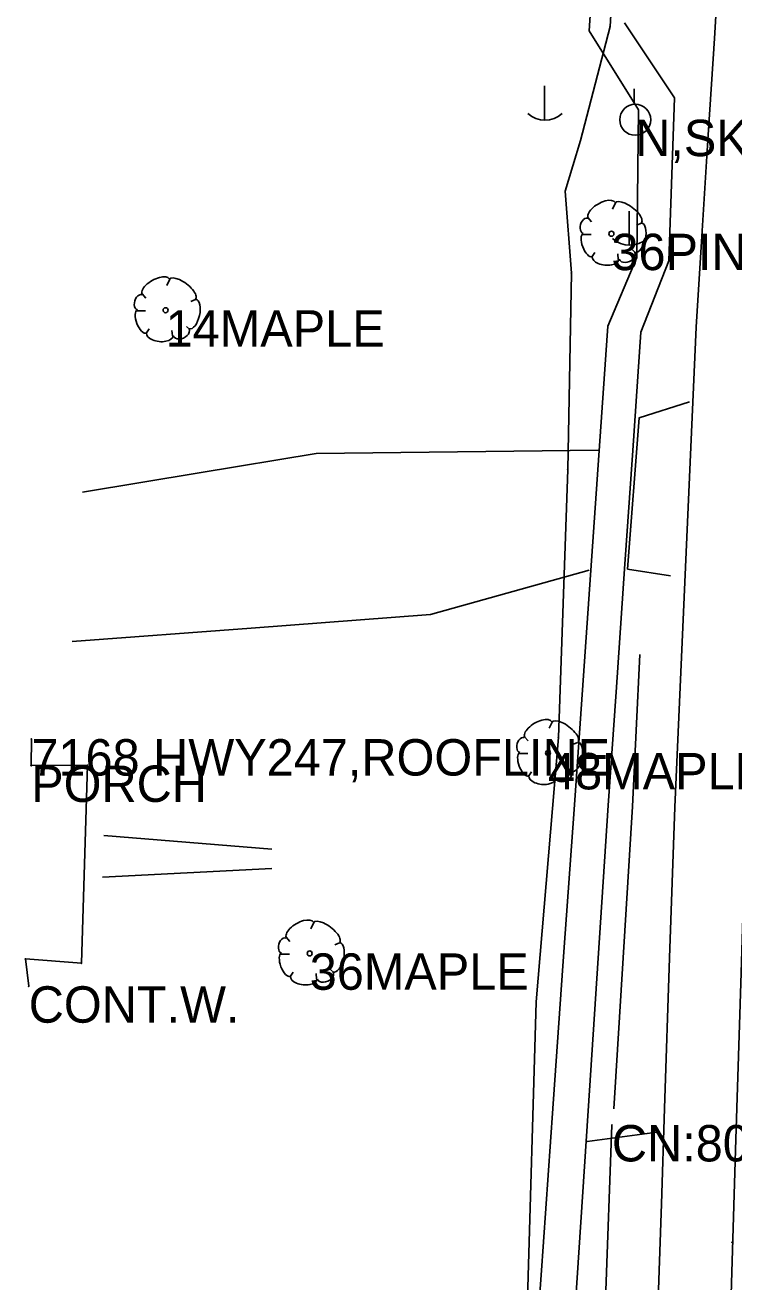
# Model space of a CAD drawing. Extents: x 997398 to 1003416, y 334596 to 337085.
# Drawn here: x 999136.5 to 999233.9, y 335108.7 to 335281.4 of the extents above; entities that cross this region are included whole.
import ezdxf

# ---------------------------------------------------------------- set-up
doc = ezdxf.new("R2010")
doc.units = 0
for name, color, linetype in [('S_BUILDING', 7, 'Continuous'), ('S_BUILDING_ANNOT', 7, 'Continuous'), ('S_DITCHLINE', 7, 'Continuous'), ('S_DRG_PT_SYM', 7, 'Continuous'), ('S_DRIVEWAY', 7, 'Continuous'), ('S_EDGE_PAVEMENT', 7, 'Continuous'), ('S_GAS_UTILITIES', 7, 'Continuous'), ('S_GRD_PT_SYM', 7, 'Continuous'), ('S_PAVEMENT_CROWN', 7, 'Continuous'), ('S_SIDE_DRAIN', 7, 'Continuous'), ('S_SIDE_DRAIN_ANNOT', 7, 'Continuous'), ('S_SIDEWALK', 7, 'Continuous'), ('S_STR_PT_SYM', 7, 'Continuous'), ('S_TREE', 7, 'Continuous'), ('S_TREE_ANNOT', 7, 'Continuous'), ('S_UTILITY_POLE', 7, 'Continuous'), ('S_UTILITY_POLE_ANNOT', 7, 'Continuous'), ('S_UTL_PT_SYM', 7, 'Continuous')]:
    doc.layers.add(name, color=color, linetype=linetype)

msp = doc.modelspace()

# ---------------------------------------------------------------- linework, layer by layer
at = {"layer": 'S_BUILDING'}
for p, q in [((999137.38, 335183.28), (999137.35, 335179.66)), ((999137.35, 335179.66), (999145.09, 335179.69)), ((999145.09, 335179.69), (999144.26, 335152.5)), ((999144.26, 335152.5), (999136.57, 335153.09)), ((999136.57, 335153.09), (999137.01, 335149.33))]:
    msp.add_line(p, q, dxfattribs=at)
at = {"layer": 'S_DITCHLINE'}
msp.add_lwpolyline([(999217.4, 335132.48), (999218.7, 335153.26), (999220, 335174.03), (999221.01, 335194.9)], dxfattribs=at)
at = {"layer": 'S_DRG_PT_SYM'}
msp.add_lwpolyline([(999217.15, 335130.27), (999217.15, 335130.32), (999217.15, 335130.27), (999217.1, 335130.27), (999217.15, 335130.27), (999217.15, 335130.22), (999217.15, 335130.27), (999217.2, 335130.27)], dxfattribs=at)
at = {"layer": 'S_DRIVEWAY'}
for points in [[(999225.22, 335205.72), (999219.3, 335206.64), (999220.88, 335227.41), (999227.82, 335229.63)], [(999215.31, 335222.96), (999195.91, 335222.74), (999176.5, 335222.52), (999160.45, 335219.88), (999144.4, 335217.23)], [(999142.96, 335196.7), (999167.6, 335198.54), (999192.24, 335200.39), (999214.03, 335206.48)], [(999213.77, 335128.01), (999223.39, 335129.3)]]:
    msp.add_lwpolyline(points, dxfattribs=at)
at = {"layer": 'S_EDGE_PAVEMENT'}
msp.add_lwpolyline([(999221.03, 335027.81), (999221.44, 335040.9), (999221.86, 335053.99), (999222.28, 335067.08), (999222.7, 335080.18), (999223.11, 335093.27), (999223.53, 335106.36), (999223.95, 335119.45), (999224.36, 335132.54), (999225.08, 335153.24), (999225.79, 335173.94), (999226.53, 335190.42), (999227.27, 335206.91), (999228, 335223.39), (999228.74, 335239.88), (999229.57, 335253.09), (999230.4, 335266.31), (999231.23, 335279.53), (999232.05, 335292.74)], dxfattribs=at)
at = {"layer": 'S_GAS_UTILITIES'}
for p, q in [((999219, 335315.47), (999216.89, 335281.18)), ((999216.89, 335281.18), (999212.84, 335265.54)), ((999212.84, 335265.54), (999210.74, 335258.54)), ((999210.74, 335258.54), (999211.59, 335247.31)), ((999211.59, 335247.31), (999211.09, 335220.34)), ((999211.09, 335220.34), (999209.79, 335183.49)), ((999209.79, 335183.49), (999206.76, 335147.2)), ((999206.76, 335147.2), (999204.1, 335055.65))]:
    msp.add_line(p, q, dxfattribs=at)
at = {"layer": 'S_GRD_PT_SYM'}
msp.add_lwpolyline([(999233.66, 335114.15), (999233.66, 335114.2), (999233.66, 335114.15), (999233.61, 335114.15), (999233.66, 335114.15), (999233.66, 335114.1), (999233.66, 335114.15), (999233.71, 335114.15)], dxfattribs=at)
at = {"layer": 'S_PAVEMENT_CROWN'}
msp.add_lwpolyline([(999231.13, 335025.58), (999231.54, 335039.84), (999231.96, 335054.1), (999232.37, 335068.37), (999232.78, 335082.63), (999233.49, 335105.48), (999234.2, 335128.32), (999234.91, 335151.16), (999235.62, 335174.01), (999236.52, 335191.6), (999237.42, 335209.19), (999238.19, 335224.55), (999238.95, 335239.91), (999239.44, 335245.85), (999240.93, 335269.15), (999242.42, 335292.45)], dxfattribs=at)
at = {"layer": 'S_SIDE_DRAIN'}
msp.add_line((999216.27, 335106.26), (999217.15, 335130.27), dxfattribs=at)
at = {"layer": 'S_SIDEWALK'}
for points in [[(999182.37, 335050.08), (999204.11, 335048.56), (999204.95, 335067.66), (999205.79, 335086.76), (999207.41, 335109.65), (999209.03, 335132.54), (999210.52, 335153.41), (999212, 335174.28), (999213.15, 335190.71), (999214.3, 335207.14), (999215.44, 335223.58), (999216.59, 335240.01), (999220.56, 335249.46), (999220.79, 335269.72), (999214.01, 335280.58), (999214.8, 335292.62)], [(999208.77, 335020.35), (999209.1, 335034.73), (999209.29, 335044.2), (999210.06, 335065.27), (999210.83, 335086.34), (999212.37, 335109.29), (999213.9, 335132.24), (999215.27, 335153.19), (999216.64, 335174.15), (999217.76, 335190.41), (999218.88, 335206.67), (999220.01, 335222.94), (999221.13, 335239.2), (999224.96, 335248.97), (999225.73, 335271.38), (999218.89, 335281.67)], [(999147.32, 335170.03), (999170.44, 335168.18)], [(999170.42, 335165.5), (999147.17, 335164.31)]]:
    msp.add_lwpolyline(points, dxfattribs=at)
at = {"layer": 'S_STR_PT_SYM'}
for points in [[(999137.38, 335183.28), (999137.38, 335183.33), (999137.38, 335183.28), (999137.33, 335183.28), (999137.38, 335183.28), (999137.38, 335183.23), (999137.38, 335183.28), (999137.43, 335183.28)], [(999137.35, 335179.66), (999137.35, 335179.71), (999137.35, 335179.66), (999137.3, 335179.66), (999137.35, 335179.66), (999137.35, 335179.61), (999137.35, 335179.66), (999137.4, 335179.66)], [(999145.09, 335179.69), (999145.09, 335179.74), (999145.09, 335179.69), (999145.04, 335179.69), (999145.09, 335179.69), (999145.09, 335179.64), (999145.09, 335179.69), (999145.14, 335179.69)], [(999136.57, 335153.09), (999136.57, 335153.14), (999136.57, 335153.09), (999136.52, 335153.09), (999136.57, 335153.09), (999136.57, 335153.04), (999136.57, 335153.09), (999136.62, 335153.09)], [(999144.26, 335152.5), (999144.26, 335152.55), (999144.26, 335152.5), (999144.21, 335152.5), (999144.26, 335152.5), (999144.26, 335152.45), (999144.26, 335152.5), (999144.31, 335152.5)], [(999137.01, 335149.33), (999137.01, 335149.38), (999137.01, 335149.33), (999136.96, 335149.33), (999137.01, 335149.33), (999137.01, 335149.28), (999137.01, 335149.33), (999137.06, 335149.33)]]:
    msp.add_lwpolyline(points, dxfattribs=at)
at = {"layer": 'S_TREE'}
for p, q in [((999217.64, 335256.96), (999217.25, 335256.11)), ((999213.84, 335254.95), (999214.35, 335254.36)), ((999221.21, 335254.17), (999220.55, 335253.9)), ((999213.18, 335252.62), (999214.31, 335252.62)), ((999214.35, 335249.44), (999214.81, 335250.14)), ((999218.03, 335249.17), (999217.95, 335249.95)), ((999220.43, 335250.06), (999219.97, 335250.49)), ((999156.38, 335246.46), (999155.99, 335245.61)), ((999152.58, 335244.44), (999153.09, 335243.86)), ((999159.94, 335243.67), (999159.29, 335243.4)), ((999151.92, 335242.12), (999153.05, 335242.12)), ((999153.09, 335238.94), (999153.55, 335239.64)), ((999156.77, 335238.67), (999156.69, 335239.44)), ((999159.17, 335239.56), (999158.7, 335239.99)), ((999208.93, 335185.63), (999208.54, 335184.78)), ((999205.13, 335183.61), (999205.63, 335183.03)), ((999212.49, 335182.84), (999211.83, 335182.57)), ((999204.47, 335181.29), (999205.6, 335181.29)), ((999205.63, 335178.11), (999206.1, 335178.81)), ((999209.32, 335177.84), (999209.24, 335178.62)), ((999211.72, 335178.73), (999211.25, 335179.16)), ((999176.18, 335158.09), (999175.79, 335157.24)), ((999172.38, 335156.08), (999172.88, 335155.49)), ((999179.74, 335155.3), (999179.08, 335155.03)), ((999171.72, 335153.75), (999172.85, 335153.75)), ((999172.88, 335150.57), (999173.35, 335151.27)), ((999176.57, 335150.3), (999176.49, 335151.08)), ((999178.97, 335151.19), (999178.5, 335151.62))]:
    msp.add_line(p, q, dxfattribs=at)
for centre in [(999217.08, 335252.71), (999155.82, 335242.21), (999208.37, 335181.38), (999175.62, 335153.85)]:
    msp.add_circle(centre, 0.341, dxfattribs=at)
for centre, major_axis, ratio, start_param, end_param in [((999215.75, 335255.92), (1.86, 1.08), 0.471018, 0, 3.141593), ((999219.4, 335255.59), (-1.81, 1.36), 0.405113, 3.141593, 6.283186), ((999213.51, 335253.8), (0.31, 1.03), 0.646762, 0, 3.141593), ((999213.82, 335251.15), (-0.61, 1.6), 0.420543, 6.283185, 9.424777), ((999220.76, 335252.18), (0.46, 2.04), 0.482994, 3.141593, 6.283185), ((999216.28, 335249.37), (-1.83, 0.19), 0.529943, 0, 3.141593), ((999219.23, 335249.66), (1.09, 0.46), 0.711534, 3.141592, 6.283185), ((999154.48, 335245.41), (1.86, 1.08), 0.471018, 0, 3.141593), ((999158.14, 335245.09), (-1.81, 1.36), 0.405113, 3.141593, 6.283186), ((999152.25, 335243.3), (0.31, 1.03), 0.646762, 0, 3.141593), ((999159.49, 335241.68), (0.46, 2.04), 0.482994, 3.141593, 6.283185), ((999152.56, 335240.65), (-0.61, 1.6), 0.420543, 6.283185, 9.424777), ((999155.02, 335238.87), (-1.83, 0.19), 0.529943, 0, 3.141593), ((999157.97, 335239.16), (1.09, 0.46), 0.711534, 3.141592, 6.283185), ((999207.03, 335184.59), (1.86, 1.08), 0.471018, 0, 3.141593), ((999210.69, 335184.26), (-1.81, 1.36), 0.405113, 3.141593, 6.283186), ((999204.8, 335182.47), (0.31, 1.03), 0.646762, 0, 3.141593), ((999212.04, 335180.85), (0.46, 2.04), 0.482994, 3.141593, 6.283185), ((999205.1, 335179.82), (-0.61, 1.6), 0.420543, 6.283185, 9.424777), ((999210.52, 335178.33), (1.09, 0.46), 0.711534, 3.141592, 6.283185), ((999207.57, 335178.04), (-1.83, 0.19), 0.529943, 0, 3.141593), ((999174.28, 335157.05), (1.86, 1.08), 0.471018, 0, 3.141593), ((999177.94, 335156.72), (-1.81, 1.36), 0.405113, 3.141593, 6.283186), ((999172.05, 335154.93), (0.31, 1.03), 0.646762, 0, 3.141593), ((999179.29, 335153.32), (0.46, 2.04), 0.482994, 3.141593, 6.283185), ((999172.35, 335152.28), (-0.61, 1.6), 0.420543, 6.283185, 9.424777), ((999177.77, 335150.79), (1.09, 0.46), 0.711534, 3.141592, 6.283185), ((999174.82, 335150.5), (-1.83, 0.19), 0.529943, 0, 3.141593)]:
    msp.add_ellipse(centre, major_axis=major_axis, ratio=ratio, start_param=start_param, end_param=end_param, dxfattribs=at)
at = {"layer": 'S_UTILITY_POLE'}
for p, q in [((999207.89, 335273.02), (999207.89, 335268.29)), ((999220.23, 335270.51), (999220.23, 335272.62)), ((999219.54, 335255.83), (999219.54, 335251.1))]:
    msp.add_line(p, q, dxfattribs=at)
msp.add_circle((999220.35, 335268.37), 2.13, dxfattribs=at)
for centre in [(999207.95, 335271.72), (999219.6, 335254.53)]:
    msp.add_arc(centre, 3.41, 226.3972, 313.6028, dxfattribs=at)
at = {"layer": 'S_UTL_PT_SYM'}
for points in [[(999216.89, 335281.18), (999216.89, 335281.23), (999216.89, 335281.18), (999216.84, 335281.18), (999216.89, 335281.18), (999216.89, 335281.13), (999216.89, 335281.18), (999216.94, 335281.18)], [(999212.84, 335265.54), (999212.84, 335265.59), (999212.84, 335265.54), (999212.79, 335265.54), (999212.84, 335265.54), (999212.84, 335265.49), (999212.84, 335265.54), (999212.89, 335265.54)], [(999210.74, 335258.54), (999210.74, 335258.59), (999210.74, 335258.54), (999210.69, 335258.54), (999210.74, 335258.54), (999210.74, 335258.49), (999210.74, 335258.54), (999210.79, 335258.54)], [(999211.59, 335247.31), (999211.59, 335247.36), (999211.59, 335247.31), (999211.54, 335247.31), (999211.59, 335247.31), (999211.59, 335247.26), (999211.59, 335247.31), (999211.64, 335247.31)], [(999211.09, 335220.34), (999211.09, 335220.39), (999211.09, 335220.34), (999211.04, 335220.34), (999211.09, 335220.34), (999211.09, 335220.29), (999211.09, 335220.34), (999211.14, 335220.34)], [(999209.79, 335183.49), (999209.79, 335183.54), (999209.79, 335183.49), (999209.74, 335183.49), (999209.79, 335183.49), (999209.79, 335183.44), (999209.79, 335183.49), (999209.84, 335183.49)], [(999206.76, 335147.2), (999206.76, 335147.25), (999206.76, 335147.2), (999206.71, 335147.2), (999206.76, 335147.2), (999206.76, 335147.15), (999206.76, 335147.2), (999206.81, 335147.2)], [(999233.66, 335114.15), (999233.66, 335114.2), (999233.66, 335114.15), (999233.61, 335114.15), (999233.66, 335114.15), (999233.66, 335114.1), (999233.66, 335114.15), (999233.71, 335114.15)]]:
    msp.add_lwpolyline(points, dxfattribs=at)

# ---------------------------------------------------------------- texts
at = {"layer": 'S_BUILDING_ANNOT'}
for s, p in [('7168 HWY247,ROOFLINE', (999137.38, 335178.28)), ('PORCH', (999137.35, 335174.66)), ('CONT.W.', (999137.01, 335144.33))]:
    msp.add_text(s, height=5, dxfattribs=at).set_placement(p)
at = {"layer": 'S_SIDE_DRAIN_ANNOT'}
msp.add_text('CN:80% FILL', height=5, dxfattribs=at).set_placement((999217.15, 335125.27))
at = {"layer": 'S_TREE_ANNOT'}
for s, p in [('36PIN OAK', (999217.08, 335247.71)), ('14MAPLE', (999155.82, 335237.21)), ('48MAPLE', (999208.37, 335176.38)), ('36MAPLE', (999175.62, 335148.85))]:
    msp.add_text(s, height=5, dxfattribs=at).set_placement(p)
at = {"layer": 'S_UTILITY_POLE_ANNOT'}
msp.add_text('N,SKIP E.', height=5, dxfattribs=at).set_placement((999220.35, 335263.37))

doc.saveas('drawing.dxf')
